// Mitsubishi GX Works2 project: 模拟量0-20mA读取   PLC: FX3U/FX3UC

PROGRAM MAIN
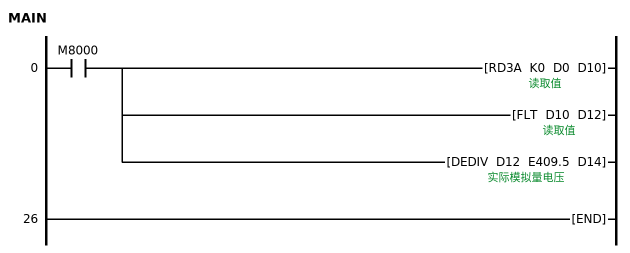
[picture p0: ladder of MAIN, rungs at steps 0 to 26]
0     LD      M8000
      RD3A    K0 D0 D10  ; 读取值
      FLT     D10 D12
      DEDIV   D12 E409.5 D14  ; 实际模拟量电压
26    END
END_PROGRAM
